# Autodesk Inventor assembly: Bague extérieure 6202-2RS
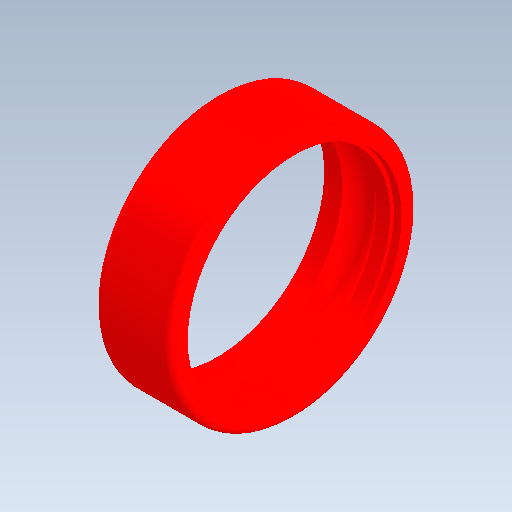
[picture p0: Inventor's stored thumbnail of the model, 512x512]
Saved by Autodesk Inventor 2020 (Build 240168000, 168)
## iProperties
Created: 2003-10
Part Number: Bague extérieure 6202-2RS
Document SubType Name: Assembly
Designer: Bruno
Author: Bruno
Sending System: SolidWorks 2011
Last Author: Professeur
Last Saved: 2014-11-10
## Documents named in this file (2)
- D:\Téléchargements-2016-17\scoot_elec\pièces à assembler\ROULEMENT 6202-2RS\Bague extérieure 6202-2RS.iam
- D:\Téléchargements-2016-17\scoot_elec\pièces à assembler\ROULEMENT 6202-2RS\Bague extérieure 6202-2RS.ipt
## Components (1 placed, 1 different names)
1. Bague extérieure 6202-2RS:1
